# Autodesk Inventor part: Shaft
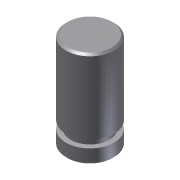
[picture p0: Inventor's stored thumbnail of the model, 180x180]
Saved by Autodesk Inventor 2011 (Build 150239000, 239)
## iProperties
Created: 2008-06
Part Number: Shaft
Document SubType Name: Modeling
Designer: CADCIM
Density: 1 g/cm^3
Author: CADCIM
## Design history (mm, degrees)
sketch "Sketch1"
  geometry: C1 r 25 at (0, 0); 1 further point
  constraints: 1 centre point, 1 coincident, 1 other
  dimensions: "d0" = 50 diameter of C1
extrude "Extrusion1" new body sketch "Sketch1" distance "d1" = 100; taper "d2" = 0 deg
chamfer "Chamfer1" distance "d3" = 2; stored, may be unused: second distance "d4" = 2, angle "d5" = 45 deg
sketch "Sketch2"
  geometry: L1 (-25, 23)-(-20, 23); L2 (-20, 23)-(-20, 15); L3 (-20, 15)-(-25, 15); L4 (-25, 15)-(-25, 23); L5 (0, -1.4)-(0, 8.4) reference; 1 further point
  constraints: 8 end point, 2 parallel, 1 horizontal, 1 perpendicular, 1 point on line, 1 other
  dimensions: "d9" = 8 distance of L3.end L1.start; "d10" = 20 distance from line of point (0, 0) L2; "d11" = 15 distance from line of L3 point (0, 0); "d13" = 25 distance from line of point (0, 0) L4
revolve "Revolution1" sketch "Sketch2" stored, may be unused: angle "d12" = 90 deg
body "Solid1"
other parameters: "d21" = 0
